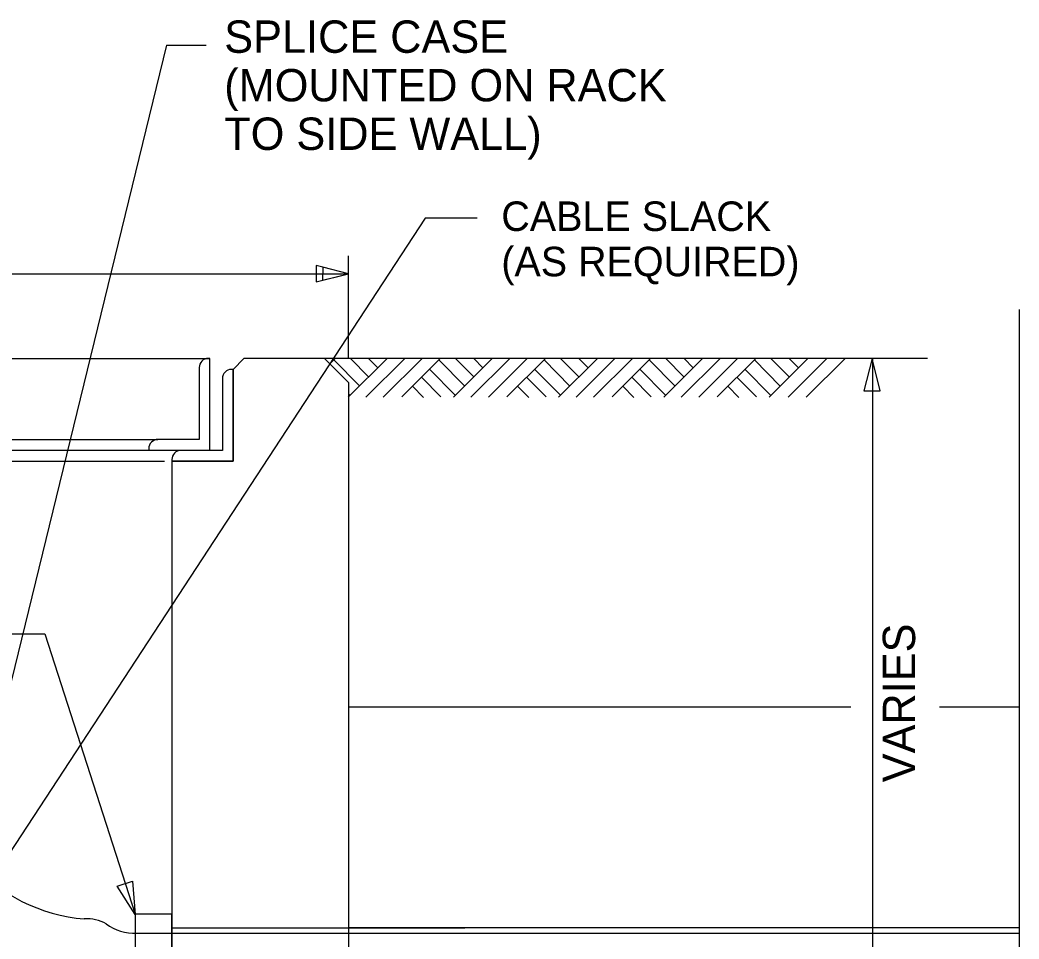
# Model space of a CAD drawing. Extents: x 1299104.8 to 1299141.6, y 239639.8 to 239661.8.
# Drawn here: x 1299128.261 to 1299131.965, y 239648.709 to 239652.117 of the extents above; entities that cross this region are included whole.
import ezdxf

# ---------------------------------------------------------------- set-up
doc = ezdxf.new("R2010")
doc.units = 0
doc.layers.add('DIM TXT', color=7, linetype='Continuous')

msp = doc.modelspace()

# ---------------------------------------------------------------- linework, layer by layer
at = {"layer": 'DIM TXT'}
for p, q in [((1299128.804, 239652.0235), (1299128.1595, 239649.3845)), ((1299128.804, 239652.0235), (1299128.9517, 239652.0232)), ((1299129.4793, 239650.8613), (1299129.4793, 239651.2424)), ((1299125.3013, 239651.1756), (1299129.4791, 239651.1753)), ((1299131.9651, 239651.0437), (1299131.9651, 239648.2643)), ((1299128.2296, 239650.8618), (1299128.9655, 239650.8618)), ((1299128.9655, 239650.8618), (1299128.9594, 239650.8618)), ((1299128.9594, 239650.8618), (1299128.9594, 239650.8618)), ((1299129.3899, 239650.8613), (1299129.0915, 239650.8613)), ((1299129.479, 239650.7722), (1299129.3899, 239650.8613)), ((1299129.4789, 239650.7723), (1299129.3899, 239650.8613)), ((1299131.6257, 239650.8613), (1299129.3899, 239650.8613)), ((1299129.4096, 239650.8416), (1299129.4294, 239650.8613)), ((1299129.4244, 239650.8563), (1299129.5206, 239650.7594)), ((1299129.4783, 239650.7182), (1299129.6225, 239650.8613)), ((1299129.486, 239650.8613), (1299129.5534, 239650.7934)), ((1299129.5432, 239650.7182), (1299129.6874, 239650.8613)), ((1299129.5534, 239650.8613), (1299129.5877, 239650.8267)), ((1299129.608, 239650.7182), (1299129.7522, 239650.8613)), ((1299129.6764, 239650.7194), (1299129.8193, 239650.8613)), ((1299129.8143, 239650.8563), (1299129.9104, 239650.7594)), ((1299129.8681, 239650.7182), (1299130.0123, 239650.8613)), ((1299129.8759, 239650.8613), (1299129.9432, 239650.7934)), ((1299129.933, 239650.7182), (1299130.0772, 239650.8613)), ((1299129.9433, 239650.8613), (1299129.9775, 239650.8267)), ((1299129.9979, 239650.7182), (1299130.1421, 239650.8613)), ((1299130.0663, 239650.7194), (1299130.2091, 239650.8613)), ((1299130.2041, 239650.8563), (1299130.3003, 239650.7594)), ((1299130.258, 239650.7182), (1299130.4022, 239650.8613)), ((1299130.2657, 239650.8613), (1299130.3331, 239650.7934)), ((1299130.3229, 239650.7182), (1299130.4671, 239650.8613)), ((1299130.3331, 239650.8613), (1299130.3674, 239650.8267)), ((1299130.3877, 239650.7182), (1299130.5319, 239650.8613)), ((1299130.4561, 239650.7194), (1299130.599, 239650.8613)), ((1299130.594, 239650.8563), (1299130.6901, 239650.7594)), ((1299130.6478, 239650.7182), (1299130.792, 239650.8613)), ((1299130.6556, 239650.8613), (1299130.7229, 239650.7934)), ((1299130.7127, 239650.7182), (1299130.8569, 239650.8613)), ((1299130.723, 239650.8613), (1299130.7572, 239650.8267)), ((1299130.7776, 239650.7182), (1299130.9218, 239650.8613)), ((1299130.846, 239650.7194), (1299130.9888, 239650.8613)), ((1299130.9838, 239650.8563), (1299131.08, 239650.7594)), ((1299131.0382, 239650.7187), (1299131.1819, 239650.8613)), ((1299131.0454, 239650.8613), (1299131.1128, 239650.7934)), ((1299131.1088, 239650.7184), (1299131.2527, 239650.8613)), ((1299131.1128, 239650.8613), (1299131.1471, 239650.8267)), ((1299131.1756, 239650.7182), (1299131.3216, 239650.8631)), ((1299131.4213, 239650.8613), (1299131.4213, 239647.5623)), ((1299129.0513, 239650.8212), (1299129.0453, 239650.8212)), ((1299129.0513, 239650.8212), (1299129.0513, 239650.4807)), ((1299129.7494, 239650.7919), (1299129.8219, 239650.7189)), ((1299129.7793, 239650.8216), (1299129.8747, 239650.7254)), ((1299130.1393, 239650.7919), (1299130.2118, 239650.7189)), ((1299130.1691, 239650.8216), (1299130.2646, 239650.7254)), ((1299130.5291, 239650.7919), (1299130.6016, 239650.7189)), ((1299130.559, 239650.8216), (1299130.6544, 239650.7254)), ((1299130.919, 239650.7919), (1299130.9915, 239650.7189)), ((1299130.9488, 239650.8216), (1299131.0443, 239650.7254)), ((1299129.4793, 239650.7719), (1299129.479, 239648.5538)), ((1299129.4793, 239650.7719), (1299129.4793, 239648.7896)), ((1299129.7159, 239650.7586), (1299129.7573, 239650.7169)), ((1299130.1058, 239650.7586), (1299130.1471, 239650.7169)), ((1299130.4956, 239650.7586), (1299130.537, 239650.7169)), ((1299130.8855, 239650.7586), (1299130.9268, 239650.7169)), ((1299129.4793, 239650.731), (1299129.4849, 239650.7254)), ((1299126.008, 239650.5614), (1299128.7725, 239650.5615)), ((1299126.0421, 239650.5213), (1299128.7385, 239650.5213)), ((1299128.7385, 239650.5274), (1299128.7385, 239650.5213)), ((1299126.2742, 239650.4807), (1299128.4396, 239650.4807)), ((1299128.4396, 239650.4807), (1299128.7974, 239650.4807)), ((1299128.8243, 239650.4867), (1299128.8243, 239650.4807)), ((1299129.0513, 239650.4807), (1299128.8243, 239650.4807)), ((1299128.8243, 239650.4807), (1299128.8243, 239649.864)), ((1299128.8243, 239649.864), (1299128.8243, 239648.1643)), ((1299129.479, 239649.8484), (1299129.479, 239648.7985)), ((1299129.4793, 239649.5699), (1299131.341, 239649.5699)), ((1299131.6706, 239649.5699), (1299131.9651, 239649.5699)), ((1299128.6938, 239648.7307), (1299131.9651, 239648.7307)), ((1299129.9108, 239648.7499), (1299128.8243, 239648.7499)), ((1299131.9651, 239648.7501), (1299129.479, 239648.7501))]:
    msp.add_line(p, q, dxfattribs=at)
for points in [[(1299129.9567, 239651.3812), (1299129.7633, 239651.3812), (1299128.1534, 239648.9236)], [(1299128.7385, 239650.5213), (1299128.9655, 239650.5213), (1299128.9655, 239650.8618)], [(1299128.9254, 239650.8278), (1299128.9254, 239650.5614), (1299128.7725, 239650.5614)], [(1299129.2703, 239650.8613), (1299129.0915, 239650.8613), (1299129.0513, 239650.8212)], [(1299128.8243, 239650.4807), (1299129.0513, 239650.4807), (1299129.0513, 239650.8212)], [(1299129.0113, 239650.7871), (1299129.0113, 239650.5208), (1299128.8584, 239650.5208)], [(1299128.0822, 239649.8412), (1299128.3529, 239649.8412), (1299128.6881, 239648.8009)]]:
    msp.add_lwpolyline(points, dxfattribs=at)
for points in [[(1299129.3589, 239651.146), (1299129.4791, 239651.1753), (1299129.3592, 239651.206)], [(1299129.3832, 239651.1521), (1299129.4793, 239651.1756), (1299129.3834, 239651.2001)], [(1299131.45, 239650.7413), (1299131.4207, 239650.8614), (1299131.39, 239650.7416)], [(1299128.6787, 239648.924), (1299128.6877, 239648.8007), (1299128.6217, 239648.9053)], [(1299128.8243, 239648.5285), (1299128.8243, 239648.8009), (1299128.6881, 239648.8009), (1299128.6881, 239648.5285)]]:
    msp.add_lwpolyline(points, close=True, dxfattribs=at)
for centre, radius, start, end in [((1299128.9594, 239650.8278), 0.034, 90, 180), ((1299129.0453, 239650.7871), 0.034, 90, 180), ((1299128.7725, 239650.5274), 0.034, 90, 180), ((1299128.8584, 239650.4867), 0.034, 90, 180), ((1299128.5526, 239649.4133), 0.6319, 221.3751, 265.1824), ((1299128.5116, 239648.6471), 0.1371, 59.7242, 95.0241), ((1299128.6833, 239648.8977), 0.1673, 232.1664, 273.5994)]:
    msp.add_arc(centre, radius, start, end, dxfattribs=at)

# ---------------------------------------------------------------- texts
for s, height, p in [('SPLICE CASE', 0.12, (1299129.0184, 239651.9948)), ('(MOUNTED ON RACK ', 0.12, (1299129.0184, 239651.8148)), ('TO SIDE WALL)', 0.12, (1299129.0184, 239651.6348)), ('CABLE SLACK', 0.109433, (1299130.0456, 239651.3343)), ('(AS REQUIRED)', 0.109433, (1299130.0456, 239651.1663))]:
    msp.add_text(s, height=height, dxfattribs=at).set_placement(p)
msp.add_text('VARIES', height=0.12, rotation=90, dxfattribs=at).set_placement((1299131.5799, 239649.2903))

doc.saveas('drawing.dxf')
